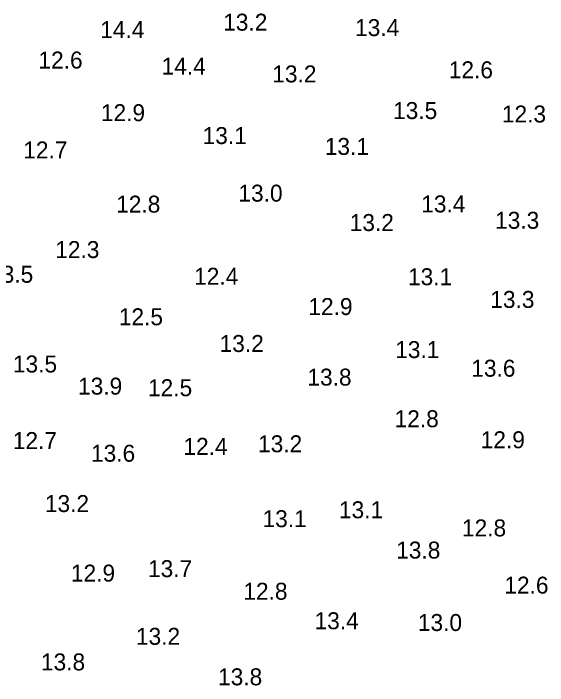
# Model space of a CAD drawing. Extents: x 815352 to 820877, y 582403 to 597439.
# Drawn here: x 817085.9 to 817243.2, y 596591.9 to 596790 of the extents above; entities that cross this region are included whole.
import ezdxf

# ---------------------------------------------------------------- set-up
doc = ezdxf.new("R2010")
doc.units = 0
doc.layers.add('V-TOPO-SOUN', color=7, linetype='Continuous')

msp = doc.modelspace()

# ---------------------------------------------------------------- texts
at = {"layer": 'V-TOPO-SOUN'}
for s, p in [('13.2 ', (817147.69, 596784.95)), ('14.4 ', (817111.47, 596782.75)), ('13.4 ', (817186.54, 596783.34)), ('12.6 ', (817093.27, 596773.79)), ('14.4 ', (817129.55, 596771.99)), ('12.6 ', (817214.14, 596770.91)), ('13.2 ', (817162.16, 596769.69)), ('13.5 ', (817197.73, 596758.9)), ('12.9 ', (817111.67, 596758.27)), ('12.3 ', (817229.78, 596757.88)), ('13.1 ', (817141.63, 596751.52)), ('12.7 ', (817088.8, 596747.28)), ('13.1 ', (817177.62, 596748.33)), ('13.0 ', (817152.18, 596734.55)), ('12.8 ', (817116.16, 596731.31)), ('13.4 ', (817206.03, 596731.37)), ('13.2 ', (817184.96, 596725.89)), ('13.3 ', (817227.78, 596726.55)), ('12.3 ', (817098.22, 596717.92)), ('13.5 ', (817078.73, 596710.64)), ('12.4 ', (817139.13, 596710.05)), ('13.1 ', (817202.13, 596709.91)), ('13.3 ', (817226.37, 596703.22)), ('12.9 ', (817172.79, 596701.12)), ('12.5 ', (817116.95, 596698.1)), ('13.2 ', (817146.64, 596690.23)), ('13.1 ', (817198.36, 596688.43)), ('13.5 ', (817085.75, 596684.19)), ('13.6 ', (817220.77, 596682.95)), ('13.8 ', (817172.5, 596680.32)), ('13.9 ', (817104.94, 596677.66)), ('12.5 ', (817125.55, 596677.2)), ('12.8 ', (817198.18, 596668.05)), ('12.9 ', (817223.55, 596661.85)), ('12.7 ', (817085.72, 596661.62)), ('12.4 ', (817135.98, 596659.91)), ('13.2 ', (817157.96, 596660.67)), ('13.6 ', (817108.76, 596657.88)), ('13.2 ', (817095.17, 596643.05)), ('13.1 ', (817181.79, 596641.21)), ('13.1 ', (817159.28, 596638.59)), ('12.8 ', (817218.03, 596635.87)), ('13.8 ', (817198.64, 596629.34)), ('12.9 ', (817102.84, 596622.55)), ('13.7 ', (817125.55, 596623.86)), ('12.6 ', (817230.51, 596619)), ('12.8 ', (817153.63, 596617.2)), ('13.4 ', (817174.6, 596608.5)), ('13.0 ', (817205.04, 596607.98)), ('13.2 ', (817122, 596603.91)), ('13.8 ', (817094.02, 596596.36)), ('13.8 ', (817146.18, 596591.97))]:
    msp.add_text(s, height=5, dxfattribs=at).set_placement(p)

doc.saveas('drawing.dxf')
